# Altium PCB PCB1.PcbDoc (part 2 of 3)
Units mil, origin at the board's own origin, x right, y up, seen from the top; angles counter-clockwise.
Board outline 6299 x 3937 mil, 12 copper layers (TopLayer, VCC, GROUND, MidLayer1, MidLayer2, MidLayer3, MidLayer4, MidLayer5, MidLayer6, MidLayer7, MidLayer8, BottomLayer); 299 components, 467 nets, 2148 pads, 429 vias.
Unrouted connection lines stored in the file: 461.
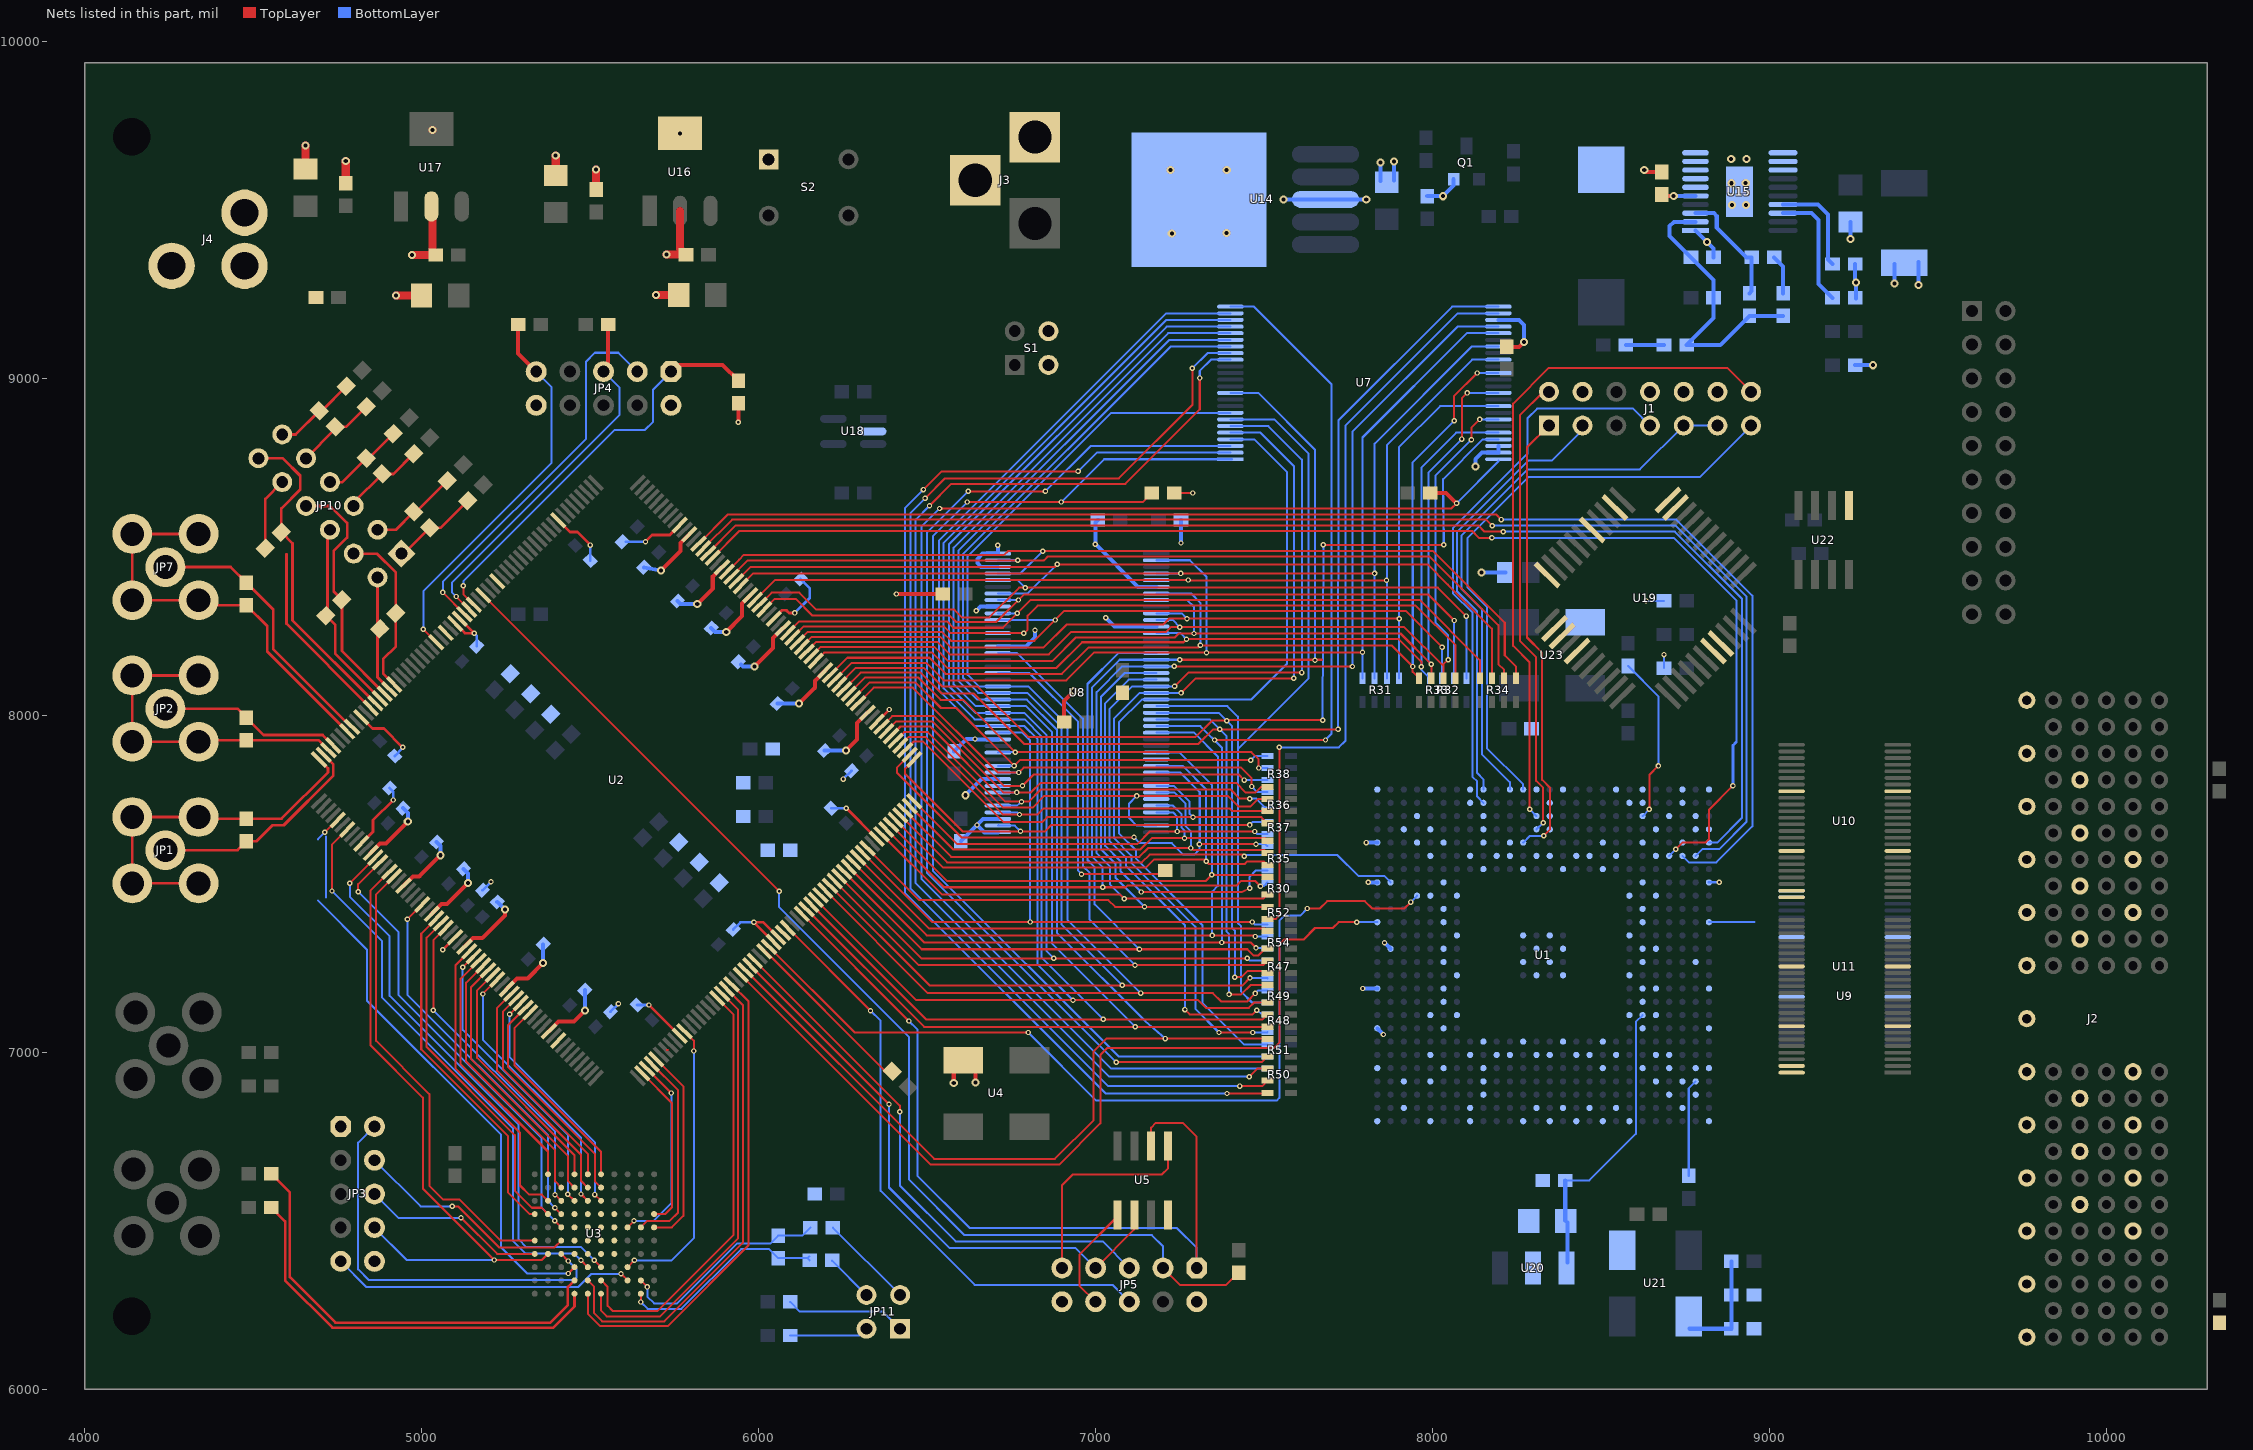
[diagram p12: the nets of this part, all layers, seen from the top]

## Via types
v1: diameter 16, hole 8, TopLayer to BottomLayer, 343 vias
v2: diameter 24, hole 12, TopLayer to BottomLayer, 84 vias
v3: diameter 56.69, hole 56.69, TopLayer to BottomLayer, 2 vias

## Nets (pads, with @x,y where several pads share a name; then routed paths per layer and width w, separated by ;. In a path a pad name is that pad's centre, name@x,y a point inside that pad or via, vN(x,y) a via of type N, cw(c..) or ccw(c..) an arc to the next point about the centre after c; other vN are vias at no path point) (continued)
101_RXLE: U2.11 U3.C3 | length 862.6
  TopLayer w6: U3.C3@5611.26,6362.74 v1(5631.52,6383) ; 5726.67,7007.33 5731.22,7007.33 ; U2.11@5780.14,7063.01 5808,7035.14 v1(5808,7004)
  BottomLayer w6: v1(5631.52,6383) 5742,6383 5808,6449 v1(5808,7004)
101_RXMODE: U2.19 U3.A5 | length 1305.6
  TopLayer w6: U3.A5@5532.52,6284 5532.52,6233.48 5549,6217 5708,6217 5939,6448 5939,7126.85 U2.19@5891.49,7174.36
101_RXOP: U2.2 U3.G1 | length 494.8
  TopLayer w6: U2.2@5654.86,6937.73 5743,6849.59 5743,6541 5722.22,6520.22 U3.G1@5690,6520.22
101_RXRATE: U2.193 U3.C5 | length 1650.6
  TopLayer w6: v1(4787,7502.18) U2.193@4862.85,7578.03 ; v1(5512.26,6383) U3.C5@5532.52,6362.74
  BottomLayer w6: v1(4787,7502.18) 4787,7462 4905,7344 4905,7168 5288,6785 5288,6445 5311,6422 5473.26,6422 v1(5512.26,6383)
101_RXST0: U2.3 U3.F3 | length 588.8
  TopLayer w6: U3.F3@5611.26,6480.85 v1(5630.41,6500) ; U2.3@5668.78,6951.65 v1(5741,6879.43)
  BottomLayer w6: v1(5630.41,6500) 5689,6500 5741,6552 v1(5741,6879.43)
101_RXST1: U2.4 U3.F2 | length 601.7
  TopLayer w6: U3.F2@5650.63,6480.85 5669.78,6500 5736,6500 5761,6525 5761,6887.27 U2.4@5682.7,6965.57
101_RXST2: U2.5 U3.F1 | length 598.9
  TopLayer w6: U3.F1@5690,6480.85 5742.85,6480.85 5777,6515 5777,6899.11 U2.5@5696.62,6979.49
101_SCSEL: U2.215 U3.K9 | length 762.7
  TopLayer w6: U2.215@5169.07,7271.8 5116,7218.73 5116,6965 5375.04,6705.96 U3.K9@5375.04,6638.33
101_SDASEL: U2.187 U3.C6 | length 1721.2
  TopLayer w6: v1(4734,7479) 4734,7616.21 U2.187@4782.79,7665 ; v1(5472.89,6383) U3.C6@5493.15,6362.74
  BottomLayer w6: v1(4734,7479) 4882,7331 4882,7164 5271,6775 5271,6441 5309,6403 5452.89,6403 v1(5472.89,6383)
101_SPDSEL: U2.185 U3.C7 | length 1777
  TopLayer w6: v1(4713,7653) 4749.38,7689.38 U2.185@4751.49,7689.38 ; v1(5435.04,6344) U3.C7@5453.78,6362.74
  BottomLayer w6: 4692,7451 4838,7305 4838,7153 5236,6755 5236,6421 5313,6344 v1(5435.04,6344) ; 4692,7632 v1(4713,7653) ; 4717,7459 4717,7640
101_T\R\S\T\Z\: JP3.8 U2.196 U3.D9 | length 1890.4
  TopLayer w6: U2.196@4904.6,7536.27 4848,7479.66 4848,7022 5004,6866 5004,6596 v1(5216,6384) 5356.93,6384 U3.D9@5375.04,6402.11
  BottomLayer w6: JP3.8@4860,6480 4956,6384 v1(5216,6384)
101_T\X\R\S\T\: U2.213 U3.H9 | length 892.3
  TopLayer w6: U2.213@5141.23,7299.64 5101,7259.4 5101,6952 5292,6761 5292,6605 5319,6578 5356.63,6578 U3.H9@5375.04,6559.59
101_TCK: JP3.4 U3.E8 | length 670.2
  TopLayer w6: v1(5091,6543) 5108,6543 5230,6421 5393.93,6421 U3.E8@5414.41,6441.48
  BottomLayer w6: JP3.4@4860,6680 4997,6543 v1(5091,6543)
101_TDI: JP3.6 U3.D10 | length 549.4
  TopLayer w6: v1(5117,6509) 5223.89,6402.11 U3.D10@5335.67,6402.11
  BottomLayer w6: JP3.6@4860,6580 4931,6509 v1(5117,6509)
101_TDO: JP3.9 U3.B3 | length 907.1
  TopLayer w6: v1(5591.63,6343) U3.B3@5611.26,6323.37
  BottomLayer w6: JP3.9@4760,6380 4836.11,6303.89 5465,6303.89 5504.11,6343 v1(5591.63,6343)
101_TMS: JP3.2 U3.D8 | length 1196.6
  TopLayer w6: U3.D8@5414.41,6402.11 v1(5435.52,6381)
  BottomLayer w6: JP3.2@4860,6780 4812,6732 4812,6356 4844,6324 5452,6324 5459,6331 5459,6357.52 v1(5435.52,6381)
101_TXCKSEL: U2.197 U3.E10 | length 1386
  TopLayer w6: U2.197@4918.52,7522.35 4865,7468.82 4865,7034 5023,6876 5023,6604 5063,6564 5112,6564 5234.52,6441.48 U3.E10@5335.67,6441.48
101_TXCLK: U2.208 U3.H8 | length 982
  TopLayer w6: v1(5035,7125) 5035,7332.6 U2.208@5071.64,7369.23 ; v1(5396,6578) U3.H8@5414.41,6559.59
  BottomLayer w6: v1(5035,7125) 5396,6764 v1(5396,6578)
101_TXCLKO+: U2.207 U3.G9 | length 1046.9
  TopLayer w6: U2.207@5057.72,7383.15 5015,7340.44 5015,7016 5276.59,6754.41 5276.59,6589.41 5327,6539 5356.26,6539 U3.G9@5375.04,6520.22
101_TXCLKO-: U2.206 U3.G10 | length 1043.6
  TopLayer w6: U2.206@5043.8,7397.07 4999,7352.27 4999,7009 5257.04,6750.96 5257.04,6583.96 5320.78,6520.22 U3.G10@5335.67,6520.22
101_TXCT0: U2.225 U3.J5 | length 669
  TopLayer w6: U2.225@5308.27,7132.6 5257,7081.34 5257,6956 5514,6699 5514,6617.48 U3.J5@5532.52,6598.96
101_TXCT1: U2.224 U3.H5 | length 713.2
  TopLayer w6: v1(5261,7113.18) U2.224@5294.35,7146.52 ; v1(5514,6578.11) U3.H5@5532.52,6559.59
  BottomLayer w6: v1(5261,7113.18) 5261,6986 5514,6733 v1(5514,6578.11)
101_TXD0: U2.216 U3.J8 | length 804.3
  TopLayer w6: U2.216@5188.11,7263 5132,7206.89 5132,6973 5396,6709 5396,6617.37 U3.J8@5414.41,6598.96
101_TXD1: U2.218 U3.K7 | length 730.3
  TopLayer w6: U2.218@5210.83,7230.04 5165,7184.21 5165,6984 5453.78,6695.22 U3.K7@5453.78,6638.33
101_TXD2: U2.217 U3.J7 | length 792.7
  TopLayer w6: U2.217@5196.91,7243.96 5147,7194.05 5147,6980 5434,6693 5434,6618.74 U3.J7@5453.78,6598.96
101_TXD3: U2.214 U3.H7 | length 877.3
  TopLayer w6: v1(5122,7252.56) U2.214@5155.15,7285.72 ; v1(5434,6579.37) U3.H7@5453.78,6559.59
  BottomLayer w6: v1(5122,7252.56) 5122,7067 5434,6755 v1(5434,6579.37)
101_TXD4: U2.223 U3.K6 | length 642.9
  TopLayer w6: U2.223@5280.43,7160.44 5241,7121.01 5241,6951 5493.15,6698.85 U3.K6@5493.15,6638.33
101_TXD5: U2.222 U3.J6 | length 704.5
  TopLayer w6: U2.222@5266.51,7174.36 5224,7131.85 5224,6945 5473,6696 5473,6619.11 U3.J6@5493.15,6598.96
101_TXD6: U2.219 U3.H6 | length 803.1
  TopLayer w6: v1(5182,7173.37) U2.219@5224.75,7216.12 ; v1(5473,6579.74) U3.H6@5493.15,6559.59
  BottomLayer w6: v1(5182,7173.37) 5182,7038 5473,6747 v1(5473,6579.74)
101_TXD7: U2.226 U3.K5 | length 605.7
  TopLayer w6: U2.226@5322.19,7118.68 5276,7072.5 5276,6961 5532.52,6704.48 U3.K5@5532.52,6638.33
101_TXMODE0: U2.20 U3.B6 | length 1425.6
  TopLayer w6: U3.B6@5493.15,6323.37 5512,6304.52 5512,6226 5536,6202 5720,6202 5953,6435 5953,7140.69 U2.20@5905.41,7188.28
101_TXMODE1: U2.21 U3.A6 | length 1445.9
  TopLayer w6: U3.A6@5493.15,6284 5493.15,6224.85 5530,6188 5730,6188 5970,6428 5970,7151.53 U2.21@5919.33,7202.2
101_TXOP: U2.203 U3.G8 | length 1125.9
  TopLayer w6: v1(4958,7394.79) U2.203@5002.04,7438.83 ; v1(5395.63,6539) U3.G8@5414.41,6520.22
  BottomLayer w6: v1(4958,7394.79) 4958,7171 5375,6754 5375,6559.63 v1(5395.63,6539)
101_TXPER: U2.194 U3.F8 | length 1359.6
  TopLayer w6: v1(4812,7477) 4812,7499.34 U2.194@4876.77,7564.11 ; v1(5395.26,6500) U3.F8@5414.41,6480.85
  BottomLayer w6: v1(4812,7477) 4932,7357 4932,7170 5356,6746 5356,6539.26 v1(5395.26,6500)
101_TXRATE: U2.18 U3.B5 | length 1278.8
  TopLayer w6: U3.B5@5532.52,6323.37 5552,6303.89 5552,6248 5568,6232 5699,6232 5925,6458 5925,7113.01 U2.18@5877.57,7160.44
AGND2: C153.1 C155.1 C157.1 C159.1 J4.2 R41.1 U19.32 U19.33
AOE#: R52.6 U2.50 U8.19 | length 2128.8
  TopLayer w6: U2.50@6322.99,7605.86 6476.86,7452 7038,7452 7058,7432 R52.6@7509.84,7432
  BottomLayer w6: v1(7145,7432) 7059.06,7517.94 7059.06,7560 7016,7603.06 7016,8055.37 7086.3,8125.67 U8.19@7180,8125.67
ARE#: R52.5 U2.53 U7.28 U8.18 | length 3929.1
  TopLayer w6: U2.53@6364.75,7647.62 6544.37,7468 7073,7468 v1(7085,7456) 7497.84,7456 R52.5@7509.84,7468 ; v1(7233.65,8145.35) 7762.35,8145.35 v1@7764,8147
  BottomLayer w6: v1(7085,7456) 7043.31,7497.69 7043.31,7551 7003,7591.31 7003,8068.94 7079.41,8145.35 v1(7233.65,8145.35) ; v1(7762,8145) 7762,8842 8073.7,9153.7 U7.28@8195.28,9153.7
AS_CONFDN: JP5.3 R26.1 U2.145 | length 3411.7
  TopLayer w6: U2.145@5182.99,8356.12 v1(6061,7478.11) ; JP5.3@7200,6360 7250,6310 7387,6310 R26.1@7420,6343
  BottomLayer w6: v1(6061,7478.11) 6061,7431 6446,7046 6446,6623 6611,6458 7167,6458 7200,6425 JP5.3@7200,6360
AS_DCLK: JP5.1 U2.36 U5.6 | length 2499.1
  TopLayer w6: U2.36@6128.12,7410.99 v1(6446,7093.11) ; U5.6@7165,6722.36 7165,6777 7179,6791 7259,6791 7300,6750 JP5.1@7300,6360
  BottomLayer w6: v1(6446,7093.11) 6471,7068.11 6471,6634 6626,6479 7241,6479 7300,6420 JP5.1@7300,6360
AS_NCONFIG: JP5.5 R27.1 U2.26 | length 1627.4
  TopLayer w6: U2.26@5988.93,7271.8 6419,6841.73 v1(6419,6824)
  BottomLayer w6: v1(6419,6824) 6419,6605 6585,6439 7021,6439 JP5.5@7100,6360
AWE#: R30.7 U2.54 U7.11 U8.17 | length 3489.6
  TopLayer w6: U2.54@6378.67,7661.54 6550.21,7490 7089,7490 7094,7495 7418,7495 7432,7509 7473,7509 v1(7489,7493) ; v1(7249.96,8165.04) 7671.04,8165.04 7672,8166
  BottomLayer w6: v1(7021,7490) 7021,7549.56 6989,7581.56 6989,8082.5 7071.54,8165.04 v1(7249.96,8165.04) ; U7.11@7400,8956.85 7482.15,8956.85 7651,8788 v1(7651,8164) ; v1(7489,7493) 7498.84,7493 R30.7@7509.84,7504
BE0#: R47.5 U2.45 U8.16 | length 2453.9
  TopLayer w6: U2.45@6253.4,7536.27 6483.66,7306 7450,7306 7468,7288 7483.34,7288 R47.5@7503.34,7308
  BottomLayer w6: v1(7130,7306) 6997,7439 6997,7549.78 6976,7570.78 6976,8093.13 7067.6,8184.73 U8.16@7180,8184.73
BE1#: R47.6 U2.43 U8.71 | length 2520.8
  TopLayer w6: U2.43@6225.56,7508.43 6474.99,7259 7496.84,7259 R47.6@7509.84,7272
  BottomLayer w6: U8.71@6710,8184.73 6767.27,8184.73 6962,7990 6962,7553.03 6982,7533.03 6982,7394 v1(7117,7259)
BE2#: R54.7 U2.47 U8.28 | length 2070
  TopLayer w6: U2.47@6281.23,7564.11 6498.34,7347 7471,7347 v1(7474,7344)
  BottomLayer w6: U8.28@7180,7948.51 7292.49,7948.51 7363,7878 7363,7494 7346,7477 v1(7346,7347) ; v1(7474,7344) R54.7@7509.84,7344
BE3#: R54.8 U2.49 U8.59 | length 1932.6
  TopLayer w6: U2.49@6309.07,7591.94 6514.02,7387 v1(7465,7387)
  BottomLayer w6: U8.59@6710,7948.51 6783,7948.51 6806,7925.51 v1(6806,7387) ; v1(7465,7387) 7472,7380 R54.8@7509.84,7380
CE0#: R30.8 U8.20 | length 1204.4
  TopLayer w6: v1(7135,7476) 7434,7476 v1(7457,7487)
  BottomLayer w6: v1(7135,7476) 7073.82,7537.18 7073.82,7567 7028,7612.82 7028,8035.87 7098.11,8105.98 U8.20@7180,8105.98 ; v1(7457,7487) 7457,7521 7476,7540 R30.8@7509.84,7540
CE1#: R52.7 U7.26 | length 2270.4
  TopLayer w6: R52.7@7509.84,7396 7535,7396 7545,7406 v1(7545,7905)
  BottomLayer w6: v1(7545,7905) 7722,7905 7741,7924 7741,8860 8074.07,9193.07 U7.26@8195.28,9193.07
CE2#: R52.8 U2.48 | length 1305
  TopLayer w6: U2.48@6295.15,7578.03 6506.18,7367 7502.84,7367 R52.8@7509.84,7360
CE3#: U1.L26 U2.23 | length 2709.1
  TopLayer w6: U2.23@5947.17,7230.04 6510.21,6667 6892,6667 7014.29,6789.29 7014.29,6992.29 7035,7013 7529,7013 7545,7029 7545,7320 7560,7335 7617,7335 7651,7369 7704,7369 7721.3,7386.3 v1(7775.3,7386.3)
  BottomLayer w6: v1(7775.3,7386.3) U1.L26@7835.75,7386.3
CVBS: J4.1 R40.2 R41.2
DATA: JP5.7 U2.25 U5.2 | length 1746.8
  TopLayer w6: U2.25@5975.01,7257.88 v1(6387,6845.89) ; JP5.7@7000,6360 7115,6475 U5.2@7115,6517.64
  BottomLayer w6: v1(6387,6845.89) 6387,6599 6567,6419 6941,6419 JP5.7@7000,6360
DSP_CLKIN: R82.2 U1.AC2 | length 288.9
  BottomLayer w6: R82.2@8760,6633.46 8760,6893.23 U1.AC2@8780.63,6913.86
DSP_T\R\S\T\: J1.2 U1.D14 | length 1386.9
  TopLayer w6: v1(8328,7681.7) 8328,7785 8307,7806 8307,8173 8259,8221 8259,8890 8329,8960 J1.2@8352,8960
  BottomLayer w6: U1.D14@8308.19,7661.89 v1(8328,7681.7)
DSP_TCLK: J1.9 J1.11 U1.A16 | length 1707.5
  BottomLayer w6: U1.A16@8229.45,7780 8229.45,7801.55 8146,7885 8146,8315 8086,8375 8086,8534 8282,8730 8615,8730 J1.9@8745,8860 J1.11@8845,8860
DSP_TDI: J1.3 U1.A18 | length 1308.1
  BottomLayer w6: U1.A18@8150.71,7780 8150.71,7810.29 8132,7829 8132,8309 8072,8369 8072,8544 8284,8756 8354,8756 8445,8847 J1.3@8445,8860
DSP_TDO: J1.7 U1.B18 | length 1666.2
  BottomLayer w6: U1.B18@8150.71,7740.63 8132,7759.34 8132,7804 8119,7817 8119,8304 8060,8363 8060,8555 8281,8776 8281,8881 8310,8910 8595,8910 J1.7@8645,8860
DSP_TMS: J1.1 U1.E15 | length 1349.2
  TopLayer w6: v1(8329.7,7642.7) 8348,7661 8348,7786 8325,7809 8325,8186 8280,8231 8280,8795 J1.1@8345,8860
  BottomLayer w6: U1.E15@8268.82,7622.52 8289,7642.7 v1(8329.7,7642.7)
EA03: R47.7 U2.77 U7.45 U8.25 | length 3941.6
  TopLayer w6: U2.77@6239.48,8091.65 6288.82,8141 6490,8141 6545.66,8085.34 6650.66,8085.34 6800,7936 7297,7936 7345.3,7984.3 v1(7388.7,7984.3) 7390.2,7985.8 v1(7673.8,7985.8) ; v1(7413,7223) 7432,7223 7450,7241 7504.84,7241 R47.7@7509.84,7236 ; v1(7675.8,8506.2) v1(8033,8506.2)
  BottomLayer w6: U8.25@7180,8007.56 7365.44,8007.56 7405,7968 7405,7369 7412,7362 ; v1(7413,7223) 7413,7362 ; v1(7673.8,7985.8) v1(7675.8,8506.2) ; v1(8033,8506.2) 8031,8701 8149.06,8819.06 U7.45@8195.28,8819.06
EA04: R47.8 U2.76 U7.25 U8.26 | length 4248
  TopLayer w6: U2.76@6253.4,8077.73 6302.66,8127 6481,8127 6543.09,8064.91 6638.09,8064.91 6788,7915 7305,7915 7348.49,7958.49 v1(7719.49,7958.49) ; v1(7396,7172) 7432,7172 7460,7200 R47.8@7509.84,7200
  BottomLayer w6: U8.26@7180,7987.88 7339.12,7987.88 7389,7938 7389,7358 7396,7351 v1(7396,7172) ; v1(7719.49,7958.49) 7720,8839 7720,8875 8057.76,9212.75 U7.25@8195.28,9212.75
  other v1: 7368.51,7958.49
EA05: R54.6 U2.46 U7.24 U8.27 | length 3930.3
  TopLayer w6: U2.46@6267.32,7550.19 6491.5,7326 7460,7326 v1(7476,7310) ; v1(7353,7927) v1(7682,7927)
  BottomLayer w6: U8.27@7180,7968.19 7310.81,7968.19 7375,7904 7375,7327 v1(7374,7326) ; U7.24@7400,9212.75 7470,9212.75 7700,8982.75 7700,7945 v1(7682,7927) ; v1(7476,7310) 7507.84,7310 R54.6@7509.84,7308
EA06: R48.5 U2.39 U7.23 U8.60 | length 4238.7
  TopLayer w6: U2.39@6169.88,7452.75 6467.63,7155 7304,7155 7327,7132 7455,7132 7471,7148 R48.5@7509.84,7148
  BottomLayer w6: v1(6933,7155) 6827,7261 6827,7930.19 6789,7968.19 6640.81,7968.19 6535,8074 6535,8518 7210.07,9193.07 U7.23@7400,9193.07
EA07: R48.6 U2.38 U7.22 U8.61 | length 4322.8
  TopLayer w6: U2.38@6155.96,7438.83 6496.79,7098 7495.84,7098 R48.6@7509.84,7112
  BottomLayer w6: v1(7023,7098) 6840,7281 6840,7937 6789.12,7987.88 6641.12,7987.88 6549,8080 6549,8512 7210.39,9173.39 U7.22@7400,9173.39
EA08: R54.5 U2.44 U7.21 U8.62 | length 3919.3
  TopLayer w6: U2.44@6239.48,7522.35 6482.82,7279 v1(7450,7279)
  BottomLayer w6: v1(6876,7279) 6854,7301 6854,7942 6788.44,8007.56 6643.44,8007.56 6565,8086 6565,8508 7210.7,9153.7 U7.21@7400,9153.7 ; v1(7450,7279) 7457,7272 R54.5@7509.84,7272
EA09: R48.7 U2.37 U7.20 U8.63 | length 4329.9
  TopLayer w6: U2.37@6142.04,7424.91 6490.95,7076 R48.7@7509.84,7076
  BottomLayer w6: v1(7118,7076) 6870,7324 6870,7951 6793.76,8027.24 6643.76,8027.24 6579,8092 6579,8498 7215.02,9134.01 U7.20@7400,9134.01
EA10: R48.8 U2.24 U7.19 U8.64 | length 4905.5
  TopLayer w6: U2.24@5961.09,7243.96 6521.05,6684 6879,6684 6994,6799 6994,7003 7032,7041 7508.84,7041 R48.8@7509.84,7040
  BottomLayer w6: v1(7207,7041) 7148,7092 6886,7354 6885,7354 6885,7958 6796.07,8046.93 6649.07,8046.93 6593,8103 6593,8488 7219.33,9114.33 U7.19@7400,9114.33
EA11: R49.8 U2.42 U7.18 U8.65 | length 4039.2
  TopLayer w6: U2.42@6211.64,7494.51 6507.15,7199 7436,7199 v1(7458,7221)
  BottomLayer w6: v1(7079,7199) 6899,7379 6899,7965 6797.39,8066.61 6651.39,8066.61 6607,8111 6607,8479 7222.65,9094.65 U7.18@7400,9094.65 ; v1(7458,7221) 7508.84,7221 R49.8@7509.84,7220
EA12: R49.7 U2.41 U7.8 U8.66 | length 4013.7
  TopLayer w6: U2.41@6197.72,7480.59 6502.31,7176 7348,7176 7373,7151 7450,7151 v1(7474,7175)
  BottomLayer w6: v1(7134,7176) 6916,7394 6916,7971 6800.7,8086.3 6653.7,8086.3 6620,8120 6620,8472 7045.8,8897.8 U7.8@7400,8897.8 ; v1(7474,7175) 7483,7184 R49.7@7509.84,7184
EA13: R49.6 U7.7 U8.24 | length 2403.5
  BottomLayer w6: U8.24@7180,8027.24 7390.76,8027.24 7422,7996 7422,7384 7432,7374 7432,7180 7464,7148 R49.6@7509.84,7148 ; U7.7@7400,8878.11 7529.89,8878.11 7632,8776 7632,8110 7422,7900
EA14: R49.5 U7.6 U8.21 | length 2745.9
  TopLayer w6: v1(7234.3,8086.3) 7275,8127 v1(7612,8127) ; v1(7265,7127) 7279,7113 7466,7113 v1(7478,7125)
  BottomLayer w6: v1(7234.3,8086.3) 7108.94,8086.3 7041,8018.36 7041,7627.57 7089.57,7579 7089.57,7553.43 7265,7378 v1(7265,7127) ; U7.6@7400,8858.42 7512.57,8858.42 7612,8759 v1(7612,8127) ; v1(7478,7125) R49.5@7496.34,7112 ; R49.5@7496.34,7110 7507.84,7110 R49.5@7509.84,7112
EA15: R51.8 U7.5 U8.22 | length 2647.1
  TopLayer w6: v1(7253.61,8066.61) 7297,8110 v1(7588,8110) ; v1(7366,7059) v1(7466,7059)
  BottomLayer w6: v1(7253.61,8066.61) 7130.59,8066.61 7054,7990.02 7054,7636.3 7106.3,7584 7106.3,7562.7 7296,7373 7296,7129 v1(7366,7059) ; U7.5@7400,8838.74 7489.26,8838.74 7588,8740 v1(7588,8110) ; v1(7466,7059) 7508.84,7059 R51.8@7509.84,7060
EA16: R51.7 U7.4 U8.23 | length 2526.2
  BottomLayer w6: U7.4@7400,8819.06 7470.94,8819.06 7568,8722 7568,8153.93 7461,8046.93 7136.93,8046.93 7069,7979 7069,7650 7120,7599 7120,7575 7317,7378 7317,7147 7440,7024 R51.7@7509.84,7024
EA17: R50.5 U7.3 | length 3270.7
  TopLayer w6: v1(6622,8665) v1(6851,8665) ; v1(7061,6971) 7492.84,6971 R50.5@7509.84,6988
  BottomLayer w6: v1(6622,8665) 6500,8543 6500,7532 v1@7064,6968 ; v1(6851,8665) 6985.37,8799.37 U7.3@7400,8799.37
EA18: R50.8 U7.2 | length 3501.6
  TopLayer w6: v1(6489,8670) 6543,8724 v1(6948,8724) ; v1(7390,6878) 7507.84,6878 R50.8@7511.84,6882
  BottomLayer w6: v1(6489,8670) 6434,8615 6434,7474 7030,6878 v1(7390,6878) ; v1(6948,8724) 7003.69,8779.68 U7.2@7400,8779.68
EA19: R51.6 R59.2 U7.1 | length 3474.6
  TopLayer w6: v1(6619,8633) 7139.54,8633 R59.2@7166.54,8660
  BottomLayer w6: v1(6619,8633) 6517,8531 6517,7539 7068,6988 R51.6@7509.84,6988 ; v1(6898,8633) 7025,8760 U7.1@7404,8760
EA20: R51.5 R58.1 U7.48 | length 4190.8
  TopLayer w6: v1(6537,8614) 8056,8614 v1(8071,8629)
  TopLayer w12: R58.1@7993.46,8660 8040,8660 v1(8071,8629)
  BottomLayer w6: v1(6537,8614) 6483,8560 6483,7515 7046,6952 R51.5@7509.84,6952 ; v1(8071,8629) 8195.28,8753.28 U7.48@8195.28,8756.28
EA21: R50.7 S1.3 U7.17 | length 3632.4
  TopLayer w6: v1(6494,8644) 6553,8703 7069,8703 7287,8921 v1(7287,9030) ; v1(7428,6900) 7493.84,6900 R50.7@7509.84,6916
  BottomLayer w6: v1(6494,8644) 6451,8601 6451,7486 7037,6900 v1(7428,6900) ; v1(7287,9030) 7331.96,9074.96 U7.17@7400,9074.96
EA22: R50.6 S1.4 U7.16 | length 3567.8
  TopLayer w6: v1(6507,8622) 6572,8687 7088,8687 7309,8908 v1(7309,9001) ; v1(7456,6928) 7480,6952 R50.6@7509.84,6952
  BottomLayer w6: v1(6507,8622) 6466,8581 6466,7502 7040,6928 v1(7456,6928) ; v1(7309,9001) 7309,9022 7342.27,9055.27 U7.16@7400,9055.27
ECLKIN: U1.H25 U2.57 | length 1554
  TopLayer w6: U2.57@6420.43,7703.3 6559.73,7564 7137,7564 7160,7587 7436,7587 v1(7441,7582)
  BottomLayer w6: v1@7444.63,7585.63 7717.52,7585.63 7779.53,7523.62 7855.9,7523.62 U1.H25@7875.12,7504.41
ECLKOUT1: R55.2 U8.68 | length 1018.5
  TopLayer w6: v1(6958,7529) 7195.54,7529 R55.2@7214.54,7548
  BottomLayer w6: U8.68@6710,8125.67 6803.33,8125.67 6948,7981 6948,7539 v1(6958,7529)
ECLKOUT2: U1.J23 U2.29 | length 2690.5
  TopLayer w6: U2.29@6030.69,7313.56 6285.24,7059 v1(6800,7059) ; v1(7628,7427) 7665,7427 7687,7449 7799,7449 7821,7427 7916,7427 v1(7935,7446)
  BottomLayer w6: v1(6800,7059) 7002,6857 7537,6857 7545,6865 7545,7391 7560,7406 7607,7406 v1(7628,7427) ; v1(7935,7446) U1.J23@7953.86,7465.04
ED00: R31.5 U2.78 U7.29 U8.2 | length 3283.3
  TopLayer w6: U2.78@6225.56,8105.57 6275.99,8156 6497,8156 6549,8104 6913,8104 6995,8186 7790,8186 v1(7792,8187)
  BottomLayer w6: U8.2@7180,8460.32 7279.69,8460.32 7329,8411 v1(7329,8186) ; R31.5@7792,8110.16 7792,8824.48 8101.53,9134.01 U7.29@8195.28,9134.01
ED01: R31.6 U2.98 U7.31 U8.4 | length 3151.6
  TopLayer w6: U2.98@5947.17,8383.96 5984.47,8421.26 v1(7827.76,8421.26)
  BottomLayer w6: U8.4@7180.31,8421.26 v1(7252.95,8421.26) ; R31.6@7828,8110.16 7828,8806.35 8116.3,9094.65 U7.31@8195.28,9094.65
ED02: R31.7 U2.95 U7.33 U8.5 | length 3122
  TopLayer w6: U2.95@5988.93,8342.2 6048.3,8401.57 v1(7274.61,8401.57) 7275.59,8400.59 v1(7863.19,8400.59)
  BottomLayer w6: U8.5@7180,8401.26 7180.31,8401.57 v1(7274.61,8401.57) ; R31.7@7864,8110.16 7864,8802 8117.27,9055.27 U7.33@8195.28,9055.27
ED03: R33.8 U2.79 U7.35 U8.7 | length 3156.5
  TopLayer w6: U2.79@6211.64,8119.49 6263.15,8171 6507,8171 6555,8123 6900,8123 6979,8202 7305,8202 v1(7311,8208) 7878,8208 v1(7941,8145) 7940.94,8129.21 R33.8@7960,8110.16 ; v1(8063.98,8874.02) 8063.98,8947.83 v1(8132.05,9015.91)
  BottomLayer w6: U8.7@7180,8361.89 7283.11,8361.89 7311,8334 v1(7311,8208) ; v1(7941,8145) 7940.94,8750.98 v1(8063.98,8874.02) ; v1(8132.05,9015.91) U7.35@8195.28,9015.91
ED04: R33.7 U2.83 U7.38 U8.8 | length 3130.5
  TopLayer w6: U2.83@6155.96,8175.17 6183.79,8203 6521,8203 6563,8161 6871,8161 6941,8231 7235,8231 7247,8243 7904.64,8243 v1@7996,8151.64 ; R33.7@7996,8110.16 v1@7996,8151.64 ; v1(7996.13,8151.64) v1@7996,8151.64 ; v1(8086.61,8819.88) 8086.61,8940.94 v1(8102.52,8956.85)
  BottomLayer w6: U8.8@7180,8342.2 7271.8,8342.2 7292,8322 v1(7292,8243) ; v1(7996.13,8151.64) 7988,8159.76 7988,8721.27 v1(8086.61,8819.88) ; v1(8102.52,8956.85) U7.38@8195.28,8956.85
ED05: R31.8 U2.85 U7.40 U8.10 | length 2962.4
  TopLayer w6: U2.85@6128.12,8203.01 6158.11,8233 6539,8233 6570,8202 6846,8202 6913.72,8269.72 7200.72,8269.72 7217.81,8286.81 v1(7900.59,8286.81)
  BottomLayer w6: U8.10@7180,8302.83 7255.24,8302.83 v1(7271.26,8286.81) ; R31.8@7900,8110.16 7900,8795 8022.48,8917.48 U7.40@8195.28,8917.48 ; v1@7900,8287.4 v1(7900.59,8286.81)
ED06: R33.6 U2.84 U7.42 U8.11 | length 2977.6
  TopLayer w6: U2.84@6142.04,8189.09 6170.95,8218 6530,8218 6567,8181 6861,8181 6928,8248 7209.19,8248 7223,8261.81 7915.35,8261.81 7975.39,8201.77 7976.38,8202.76 8032,8147.13 ; R33.6@8032,8110.16 8032,8151.09 v1(8046.26,8165.35) ; v1(8115.16,8818.16) 8115.16,8853.35 v1(8139.92,8878.11)
  BottomLayer w6: U8.11@7180,8283.15 7228.66,8283.15 v1(7250,8261.81) ; v1(8046.26,8165.35) 8046.26,8238.19 8008,8276.45 8008,8711 v1(8115.16,8818.16) ; v1(8139.92,8878.11) U7.42@8195.28,8878.11
ED07: R32.5 U2.82 U7.44 U8.13 | length 2908.2
  TopLayer w6: U2.82@6169.88,8161.25 6194.63,8186 6515,8186 6560,8141 6884,8141 6960,8217 7260.78,8217 v1(7269.78,8226) 7900,8226 7966.54,8159.46 v1(7966.54,8144)
  BottomLayer w6: U8.13@7180,8243.78 7252,8243.78 v1(7269.78,8226) ; R32.5@7992,8110.16 7966.54,8135.62 7966.54,8735.24 8070.04,8838.74 U7.44@8195.28,8838.74
ED08: R33.5 U2.87 U8.74 | length 2271.5
  TopLayer w6: U2.87@6100.28,8230.85 6133.44,8264 6550,8264 6570.22,8243.78 v1(6787.09,8243.78) 6798,8254.69 6798,8296 6827.79,8325.79 7949.8,8325.79 8068,8207.59 R33.5@8068,8110.16
  BottomLayer w6: U8.74@6710,8243.78 v1(6787.09,8243.78)
ED09: R32.6 U2.86 U8.76 | length 2282.1
  TopLayer w6: U2.86@6114.2,8216.93 6145.27,8248 6544,8248 6571,8221 6818.44,8221 6907.48,8310.04 7920.28,8310.04 v1(8028,8202.32)
  BottomLayer w6: U8.76@6710,8283.15 v1(6880.59,8283.15) ; R32.6@8028,8110.16 v1(8028,8202.32)
ED10: R34.8 U2.88 U8.77 | length 2295.1
  TopLayer w6: U2.88@6086.36,8244.77 6120.6,8279 6559,8279 6578,8260 6724.57,8260 6807.09,8342.52 7961.61,8342.52 8140,8164.13 R34.8@8140,8110.16
  BottomLayer w6: U8.77@6710,8302.83 v1(6767.4,8302.83)
ED11: R32.7 U2.93 U8.79 | length 2387.5
  TopLayer w6: U2.93@6016.77,8314.36 6048.4,8346 6110,8346 6160,8296 6567,8296 6586,8277 6705.78,8277 6788.03,8359.25 7986.22,8359.25 v1(8064,8281.47)
  BottomLayer w6: U8.79@6710,8342.2 v1(6770.98,8342.2) ; R32.7@8064,8110.16 v1(8064,8281.47)
ED12: R34.7 U2.99 U8.80 | length 2700.9
  TopLayer w6: U2.99@5933.25,8397.88 5975.37,8440 6878,8440 v1(6886,8448) 7985.07,8448 8044.98,8388.09 8176,8257.07 R34.7@8176,8110.16
  BottomLayer w6: U8.80@6710,8361.89 6798.9,8361.89 v1(6886,8448)
ED13: R32.8 U2.94 U8.82 | length 2487.9
  TopLayer w6: U2.94@6002.85,8328.28 6038.56,8364 6121,8364 6171,8314 6581,8314 ; 6581,8313 6603,8291 6685,8291 6772.94,8378.94 8015.75,8378.94 v1(8100,8294.68)
  BottomLayer w6: U8.82@6710,8401.26 6768.74,8401.26 v1(6791.06,8378.94) ; R32.8@8100,8110.16 v1(8100,8294.68)
ED14: R34.5 U2.101 U8.83 | length 2764
  TopLayer w6: U2.101@5903.69,8424 U2.101@5905.41,8425.72 5942.07,8462.38 5955.69,8476 6728.8,8476 6740,8487.2 8001.8,8487.2 8214,8275 8214,8178 8248,8144 R34.5@8248,8110.16
  BottomLayer w6: U8.83@6710,8420.94 6776.94,8420.94 v1(6843.2,8487.2)
ED15: R34.6 U2.100 U8.85 | length 2609.3
  TopLayer w6: U2.100@5919.33,8411.8 5967.53,8460 6847.31,8460 ; 6847,8460.32 6858.69,8472 7990.6,8472 8195,8267.6 8195,8152 8212,8135 R34.6@8212,8110.16
  BottomLayer w6: U8.85@6710,8460.32 v1(6769.37,8460.32)
ED16: R35.8 U2.55 U8.31 | length 1668.5
  TopLayer w6: U2.55@6392.59,7675.46 6560.05,7508 7326,7508 v1(7345,7527) 7503.84,7526 R35.8@7509.84,7520
  BottomLayer w6: U8.31@7180,7889.45 7249.55,7889.45 7345,7794 v1(7345,7527)
ED17: R35.7 U2.56 U8.33 | length 1576
  TopLayer w6: U2.56@6406.51,7689.38 6547.89,7548 7149,7548 7174,7573 7322,7573 7336,7559 7442,7559 7450,7567 7498.84,7567 R35.7@7509.84,7556
  BottomLayer w6: U8.33@7180,7850.08 7258,7850.08 7328,7780.08 v1(7328,7567)
ED18: R37.5 U2.62 U8.34 | length 1600.7
  TopLayer w6: U2.62@6448.27,7882.86 6411,7845.59 6411,7829 6602,7638 v1(7114,7638) ; v1(7308,7618) v1(7476,7618)
  BottomLayer w6: v1(7114,7638) 7131,7621 7226,7621 7260,7587 7293,7587 7308,7602 v1(7308,7618) 7309,7619 7309,7772 7250.6,7830.4 U8.34@7180,7830.4 ; v1(7476,7618) 7503.84,7618 R37.5@7509.84,7612
ED19: R36.8 U2.63 U8.36 | length 1367.2
  TopLayer w6: U2.63@6434.35,7896.78 6459.57,7922 6488,7922 6727,7683 6841,7683 6856,7698 7491.84,7698 R36.8@7509.84,7680
  BottomLayer w6: U8.36@7180,7791.02 7232,7791.02 7279,7744.02 7279,7708 v1(7289,7698)
ED20: R35.6 U2.58 U8.37 | length 1379.4
  TopLayer w6: U2.58@6434.35,7717.22 6571.57,7580 7130,7580 7156.52,7606.52 v1(7282.48,7606.52) ; 7288.61,7600.39 7501.45,7600.39 R35.6@7509.84,7592
  BottomLayer w6: U8.37@7180,7771.34 7233.66,7771.34 7267,7738 7267,7671.58 7282.48,7656.1 v1(7282.48,7606.52)
ED21: R35.5 U2.59 U8.39 | length 1292.2
  TopLayer w6: U2.59@6448.27,7731.14 6577.41,7602 7133,7602 7166.83,7635.83 7502.02,7635.83 R35.5@7509.84,7628
  BottomLayer w6: U8.39@7180,7731.97 7229.64,7731.97 7255,7706.61 7255,7666.61 7263.78,7657.83 v1(7263.78,7635.83)
ED22: R37.6 U2.60 U8.40 | length 1230.5
  TopLayer w6: U2.60@6462.19,7745.06 6589.25,7618 7123,7618 7160.51,7655.51 v1(7472.44,7655.51)
  BottomLayer w6: U8.40@7180,7712.28 7229.64,7712.28 7242.13,7699.8 v1(7242.13,7655.51) ; v1(7472.44,7655.51) 7479.95,7648 R37.6@7509.84,7648
ED23: R36.6 U2.65 U8.42 | length 1408.2
  TopLayer w6: U2.65@6406.51,7924.62 6431.89,7950 6502,7950 6726,7726 6813,7726 6848,7761 7392,7761 7423,7730 7460,7730 7482,7752 R36.6@7509.84,7752
  BottomLayer w6: v1(7122,7761) 7099,7738 7099,7696 7122.09,7672.91 U8.42@7180,7672.91
ED24: R37.7 U2.61 U8.45 | length 1288
  TopLayer w6: U2.61@6462.19,7868.94 6435,7841.75 6435,7826 6605,7656 6850,7656 6869,7675 v1(7457,7675)
  BottomLayer w6: U8.45@6712.09,7675 U8.45@6710,7672.91 6760.09,7672.91 v1(6777,7656) ; v1(7457,7675) 7466,7684 R37.7@7509.84,7684
ED25: R36.7 U2.64 U8.47 | length 1272
  TopLayer w6: U2.64@6420.43,7910.7 6445.73,7936 6494,7936 6724,7706 6828,7706 6845,7723 7398,7723 7405,7716 R36.7@7509.84,7716
  BottomLayer w6: U8.47@6710,7712.28 6768,7712.28 v1(6774.28,7706)
ED26: R37.8 U2.66 U8.48 | length 1335.8
  TopLayer w6: U2.66@6392.59,7938.54 6421.05,7967 6509,7967 6731.94,7744.06 v1(6780.15,7744.06) ; v1@6780.16,7744.38 6801.06,7744.06 6837,7780 7401,7780 7428,7753 v1(7457,7753)
  BottomLayer w6: U8.48@6710,7731.97 6766.06,7731.97 v1(6780.15,7744.06) ; v1(7457,7753) 7476.84,7753 R37.8@7509.84,7720
ED27: R36.5 U2.67 U8.50 | length 1317.8
  TopLayer w6: U2.67@6378.67,7952.46 6408.21,7982 6515,7982 6725.66,7771.34 6808.34,7771.34 6837,7800 7416.76,7800 7446.01,7770.75 7473.75,7770.75 7491,7788 R36.5@7509.84,7788
  BottomLayer w6: U8.50@6710,7771.34 v1(6766,7771.34)
ED28: R38.6 U2.68 U8.51 | length 1338.2
  TopLayer w6: U2.68@6364.75,7966.38 6396.37,7998 6521,7998 6727.98,7791.02 v1(6783.15,7791.02) 6817.13,7825 7424,7825 v1(7441,7808)
  BottomLayer w6: U8.51@6710,7791.02 v1(6783.15,7791.02) ; v1(7441,7808) R38.6@7509.84,7808
ED29: R38.5 U2.73 U8.53 | length 1450.9
  TopLayer w6: U2.73@6295.15,8035.97 6341.18,8082 6458,8082 6709.6,7830.4 v1(6772,7830.4) 6786.6,7845 7432,7845 7463,7814 v1(7463,7789)
  BottomLayer w6: U8.53@6710,7830.4 v1(6772,7830.4) ; v1(7463,7789) 7480,7772 R38.5@7509.84,7772
ED30: R38.8 U2.74 U8.54 | length 1411.6
  TopLayer w6: U2.74@6281.23,8049.89 6329.34,8098 6465,8098 6541.12,8021.88 6586.2,8021.88 v1(6758,7850.08) 6774.92,7867 v1(7460.5,7867)
  BottomLayer w6: U8.54@6710,7850.08 v1(6758,7850.08) ; v1(7460.5,7867) 7473.5,7880 R38.8@7509.84,7880
ED31: R38.7 U2.75 U8.56 | length 1441.5
  TopLayer w6: U2.75@6267.32,8063.81 6316.5,8113 6473,8113 6540.12,8045.88 6606.68,8045.88 v1(6761.81,7890.75) 7462.25,7890.75 7483.76,7869.24 v1(7483.76,7844)
  BottomLayer w6: U8.56@6710,7889.45 6711.3,7890.75 v1(6761.81,7890.75) ; v1(7483.76,7844) R38.7@7509.84,7844
EMU0: J1.13 U1.A15 | length 1794.2
  BottomLayer w6: U1.A15@8268.82,7780 8268.82,7795.18 8161,7903 8161,8322 8104,8379 8104,8527 8284,8707 8792,8707 J1.13@8945,8860
EMU1: J1.14 U1.C14 | length 2031.7
  TopLayer w6: v1(8288,7721.45) 8288,8157 8239,8206 8239,8925 8345,9031 8874,9031 J1.14@8945,8960
  BottomLayer w6: v1(8288,7721.45) U1.C14@8308.19,7701.26
FPGA_ASDO: JP5.9 U5.5 | length 647.5
  TopLayer w6: JP5.9@6900,6360 6900,6605 6933,6638 7197,6638 7215,6656 U5.5@7215,6722.36
FPGA_NCSO: JP5.8 U5.1 | length 324.3
  TopLayer w6: JP5.8@7000,6260 6952,6308 6952,6400 7065,6513 U5.1@7065,6517.64
GCLK0: R25.2 U2.153
GCLK1: R24.2 U2.28 | length 510.6
  TopLayer w6: U2.28@6016.77,7299.64 6020.36,7299.64 6376.34,6943.66 R24.2@6372.74,6943.66
GND: C5.1 C6.1 C7.1 C8.1 C9.1 C10.1 C11.1 C12.1 C13.1 C14.1 C15.1 C16.1 C17.1 C18.1 C19.1 C20.1 C21.1 C22.1 C23.1 C24.1 C25.1 C26.1 C32.1 C36.1 C37.2 C38.2 C39.2 C40.2 C41.2 C45.2 C46.2 C47.2 C48.2 C49.2 C54.1 C55.2 C56.2 C57.2 C58.2 C59.2 C64.1 C65.2 C66.2 C67.2 C68.2 C69.2 C73.2 C74.2 C75.2 C76.2 C77.2 C82.2 C83.2 C84.2 C85.2 C86.2 C95.1 C96.1 C97.2 C98.2 C99.2 C100.2 C101.2 C103.2 C104.2 C105.2 C106.2 C107.2 C108.2 C109.2 C110.2 C111.2 C112.2 C114.2 C115.2 C116.2 C117.2 C119.2 C120.2 C121.2 C123.2 C124.2 C125.1 C126.1 C127.1 C128.1 C129.1 C130.1 C131.1 C132.1 C133.1 C134.2 C135.2 C136.2 C137.2 C138.2 C139.2 C140.2 C141.2 C142.2 C143.2 C144.2 C146.2 C147.2 C150.2 C152.2 C154.1 C156.1 C158.1 C160.1 C161.1 C162.1 C163.1 C164.2 C165.1 C166.1 DS6.2 DS7.2 DS9.2 J1.4 J1.8 J1.10 J1.12 J2.B5 J2.B7 J2.B9 J2.B11 J2.B17 J2.B19 J2.D6 J2.D8 J2.D10 J2.D16 J2.D18 J2.D20 J2.D22 J2.F1 J2.F3 J2.F5 J2.F7 J2.F9 J2.F11 J2.F13 J2.F15 J2.F17 J2.F19 J2.F21 J2.F23 J2.F25 J3.2 J3.3 JP3.1 JP3.10 JP4.2 JP4.10 JP5.2 JP5.10 Q1.3 R15.2 R17.1 R18.2 R19.2 R20.2 R21.2 R22.1 R23.1 R28.1 R39.2 R59.1 R60.1 R65.1 R67.1 R83.1 R84.1 S2.1 U1.A1 U1.A3 U1.A6 U1.A8 U1.A12 U1.A14 U1.A19 U1.A22 U1.A26 U1.AA4 U1.AA5 U1.AA8 U1.AA10 U1.AA11 U1.AA13 U1.AA14 U1.AA16 U1.AA17 U1.AA19 U1.AA22 U1.AB1 U1.AB2 U1.AB4 U1.AB6 U1.AB9 U1.AB18 U1.AB21 U1.AB26 U1.AC3 U1.AC5 U1.AC18 U1.AC22 U1.AC24 U1.AD2 U1.AD4 U1.AD18 U1.AE3 U1.AE8 U1.AE10 U1.AE12 U1.AE14 U1.AE19 U1.AE24 U1.AF1 U1.AF7 U1.AF9 U1.AF11 U1.AF13 U1.AF15 U1.AF19 U1.AF22 U1.AF26 U1.B3 U1.B6 U1.B7 U1.B13 U1.B19 U1.C2 U1.C4 U1.C13 U1.C18 U1.C23 U1.D1 U1.D2 U1.D5 U1.D13 U1.D18 U1.D22 U1.D24 U1.E3 U1.E6 U1.E9 U1.E16 U1.E18 U1.E21 U1.E23 U1.E26 U1.F5 U1.F8 U1.F10 U1.F11 U1.F13 U1.F14 U1.F16 U1.F17 U1.F19 U1.F22 U1.G9 U1.G12 U1.G15 U1.G18 U1.H1 U1.H6 U1.H21 U1.H26 U1.J5 U1.J7 U1.J20 U1.J22 U1.K6 U1.K21 U1.L1 U1.L6 U1.L21 U1.M7 U1.M13 U1.M15 U1.M20 U1.N5 U1.N6 U1.N12 U1.N14 U1.N21 U1.N25 U1.P2 U1.P6 U1.P13 U1.P15 U1.P21 U1.R7 U1.R12 U1.R14 U1.R20 U1.T1 U1.T5 U1.T6 U1.T21 U1.T26 U1.U6 U1.U21 U1.V5 U1.V7 U1.V20 U1.V22 U1.W1 U1.W6 U1.W21 U1.W26 U1.Y9 U1.Y12 U1.Y15 U1.Y18 U2.10 U2.30 U2.31 U2.40 U2.52 U2.69 U2.71 U2.80 U2.89 U2.91 U2.96 U2.102 U2.109 U2.111 U2.129 U2.142 U2.150 U2.151 U2.171 U2.190 U2.192 U2.199 U2.205 U2.210 U2.212 U2.221 U2.230 U2.232 U3.D4 U3.D5 U3.D6 U3.D7 U3.E4 U3.E5 U3.E6 U3.E7 U3.F4 U3.F5 U3.F6 U3.F7 U3.G4 U3.G5 U3.G6 U3.G7 U4.2 U5.4 U6.2 U7.27 U7.46 U7.47 U8.6 U8.12 U8.32 U8.38 U8.44 U8.46 U8.52 U8.58 U8.72 U8.78 U8.84 U8.86 U9.8 U9.17 U9.32 U9.41 U9.47 U9.48 U10.8 U10.17 U10.32 U10.41 U10.47 U10.48 U11.8 U11.17 U11.32 U11.41 U11.47 U11.48 U14.3 U15.1 U15.11 U15.12 U15.13 U16.2@5767,9727 U17.2@5029,9510 U18.2 U19.2 U19.3 U19.5 U19.18 U19.19 U19.35 U19.38 U19.44 U20.2 U21.2 U22.5 U23.2 | length 8598.5
  TopLayer w6: R59.1@7233.46,8660 v1(7288,8660)
  TopLayer w8: U2.190@4821.09,7619.78 4856,7654.7 4856,7689 v1(4916,7749) ; U2.171@4821.09,7994.22 4854.3,7961 4888,7961 v1(4944,7905) ; v1(5063,7304.92) U2.210@5099.48,7341.4 ; U2.151@5099.48,8272.6 5128.16,8243.92 v1(5156,8243.92) U2.150@5113.4,8286.52 ; U2.129@5405.7,8578.83 5440.54,8544 5462,8544 v1(5500.7,8505.3) ; v1(5664.46,8515.46) 5684,8535 5736.3,8535 U2.111@5766.22,8564.91 ; v1(5674.6,7140.7) U2.10@5766.22,7049.09 ; U2.30@6044.6,7327.48 v1(5986.08,7386) 6013.92,7386 U2.31@6058.52,7341.4 ; U2.91@6044.6,8286.52 6070.08,8312 6082,8312 6090,8304 v1(6107,8304) ; v1(6259.99,7724.54) U2.52@6350.83,7633.7 ; U2.69@6350.83,7980.3 v1(6388,8017.46)
  TopLayer w12: U2.192@4848.93,7591.94 4876.98,7620 4894,7620 v2(4959,7685) ; U2.199@4946.36,7494.51 4973.85,7522 4993,7522 v2(5056,7585) ; U2.205@5029.88,7410.99 5058.89,7440 5076,7440 v2(5138,7502) ; U2.212@5127.31,7313.56 5152.76,7339 5180,7339 5247,7406 v2(5247,7424.08) ; U2.221@5252.59,7188.28 5283.31,7219 5315,7219 v2(5360.7,7264.7) ; U2.230@5377.86,7063.01 5406.86,7092 5452,7092 v2(5484.54,7124.54) ; v2(5710,8430) 5768,8488 5768,8511.02 U2.109@5794.06,8537.07 ; v2(5818,8330) 5864,8376 5864,8412.15 U2.102@5891.49,8439.64 ; v2(5904,8248) 5951,8295 5951,8332.11 U2.96@5975.01,8356.12 ; v1(5940,8870) R17.1@5940,8926.54 ; v2(5988,8145) 6043,8200 6043,8229.24 U2.89@6072.44,8258.69 ; v2(6120.46,8035.46) 6167,8082 6167,8102.69 U2.80@6197.72,8133.41 ; v2(6259.46,7895.46) 6292,7928 6292,7977.14 U2.71@6322.99,8008.14 ; v1(6409,8360) C20.1@6546.54,8360 ; v2(6579,6909) U4.2@6579,6958 ; v2(6644,6911) U4.2@6644,6957 ; C26.1@6906.54,7980 6906.54,8042.54 v2(6936,8072) ; C19.1@8232.46,9093.46 8256.46,9093.46 v2(8271,9108)
  TopLayer w24: C139.2@4655,9621.12 v2(4655,9691) ; C127.1@4775,9579.46 v2(4775,9645) ; v2(4924,9246) C143.2@4999.88,9246 ; v2(4971,9366) C132.1@5041.54,9366 5032,9375.54 U17.2@5032,9507 ; C136.2@5398,9602.12 v2(5398,9661) ; C96.1@5518,9560.46 v2(5518,9620) ; v2(5696,9247) C137.2@5762.88,9247 ; v2(5727,9367) C125.1@5784.54,9367 5767,9384.54 5767,9497
  BottomLayer w6: v1(8633,8340) R83.1@8686.54,8340 ; R84.1@8686.54,8140 v1(8686.54,8180.46) ; U1.L1@8820,7386.3 8954.7,7386.3
  BottomLayer w8: C98.2@4904.54,7784.54 4916,7773.08 v1(4916,7749) ; C108.2@4920.7,7879.3 4944,7902.6 v1(4944,7905) ; v1(5156,8243.92) 5163.76,8236.16 C103.2@5163.76,8205.31 ; C99.2@5180.7,7480.7 v1(5206,7506) ; C97.2@5500.7,8459.3 v1(5500.7,8505.3) ; C105.2@5560.7,7120.7 v1(5584,7144) ; C119.2@5605.54,8515.46 v1(5664.46,8515.46) ; C104.2@5639.3,7140.7 v1(5674.6,7140.7) ; C115.2@5924.54,7364.54 5946,7386 v1(5986.08,7386) ; v1(6107,8304) 6152,8349 6152,8377.08 C114.2@6124.54,8404.54 ; C109.2@6215.46,7724.54 v1(6259.99,7724.54) ; v1(6251,7811) C110.2@6275.46,7835.46 ; U1.H1@8820,7504.41 v1(8850.41,7504.41)
  BottomLayer w12: C100.2@4944.54,7724.54 4959,7710.08 v2(4959,7685) ; C106.2@5044.54,7624.54 5056,7613.08 v2(5056,7585) ; C111.2@5124.54,7544.54 5138,7531.08 v2(5138,7502) ; C116.2@5224.54,7446.54 v2(5247,7424.08) ; v2(5360.7,7264.7) C123.2@5360.7,7320.7 ; v2(5484.54,7124.54) C120.2@5484.54,7184.54 ; C124.2@5659.3,8439.3 v2(5710,8430) ; C112.2@5759.3,8339.3 5768.6,8330 v2(5818,8330) ; C101.2@5859.3,8259.3 5870.6,8248 v2(5904,8248) ; C121.2@5948,8150.6 5953.6,8145 v2(5988,8145) ; C117.2@6055.46,8035.46 v2(6120.46,8035.46) ; C107.2@6195.46,7895.46 v2(6259.46,7895.46) ; C21.1@6580,7893.46 6616.54,7930 v1(6642,7930) 6643.18,7928.82 U8.58@6710,7928.82 ; C22.1@6600,7626.54 v1(6648.11,7674.65) ; v2(6614,7763) 6661.71,7810.71 U8.52@6710,7810.71 ; v1(6646,8310) 6658.52,8322.52 U8.78@6710,8322.52 ; U8.44@6710,7653.23 6669.53,7653.23 v1(6648.11,7674.65) ; U8.46@6710,7692.6 6666.06,7692.6 v1(6648.11,7674.65) ; U8.72@6710,8204.41 6793.41,8204.41 6820,8231 v1(6820,8253) ; U8.84@6710,8440.63 6660.37,8440.63 6649,8452 6649,8464 6665,8480 U8.86@6710,8480 v1(6710,8505) ; C24.1@7006.54,8580 6999,8572.46 v1(6999,8508) 7125.43,8381.58 U8.6@7180,8381.58 ; v1(7030,8290) 7056.53,8263.47 U8.12@7180,8263.47 ; v1(7253.46,8511.54) C23.1@7253.46,8580 ; v2(7557,9531) v2(7803,9531) ; v1(7792.84,7189.45) U1.T26@7835.75,7189.45 ; v1(7802.68,7622.52) U1.E26@7835.75,7622.52 ; v1(7808.58,7504.41) U1.H26@7835.75,7504.41 ; U1.W26@7835.75,7071.34 v1(7853.94,7053.15) ; C135.2@7845,9585 v2(7845,9641) ; v1(7857.28,7325.39) U1.N25@7875.12,7307.56 ; C135.2@7885,9587 v2(7885,9644) ; C95.1@7984,9540.46 v2(8030.46,9540.46) 8062.6,9572.6 Q1.3@8062.6,9590.79 ; v2(8127,8739) 8127,8760 8146.69,8779.68 U7.47@8195.28,8779.68 U7.46@8195.28,8799.37 ; v2(8145,8424) DS9.2@8216.6,8424 ; U7.27@8195.28,9173.39 8255.61,9173.39 8271,9158 v2(8271,9108) ; U15.1@8780,9439 8833.46,9385.54 R67.1@8833.46,9359 ; v2(9240,9413) C146.2@9240,9463.88 ; R65.1@9253.46,9039 v2(9307,9039) ; C64.1@9253.46,9339 9253.46,9287.54 v2(9256,9285) C54.1@9256,9237 ; v2(9370,9282) C134.2@9370,9340 ; v2(9442,9277) C134.2@9442,9345
  other v2: 8813.99,9405.01 7226,9430 7388,9431 8888,9514 8930,9514 8887,9579 8929,9580 7222,9618 7389,9618 8886,9651 8931,9651 5767,9727 5032,9737
GP02: R86.1 U1.C6 | length 502
  TopLayer w6: v1(8643,7721.11) 8643,7823 v1(8670,7850)
  BottomLayer w6: R86.1@8580,8146.54 8670,8056.54 v1(8670,7850) ; U1.C6@8623.15,7701.26 v1(8643,7721.11)
GP04: U1.F4 U2.104 | length 4036.5
  TopLayer w6: U2.104@5863.65,8467.48 5943.18,8547 8117,8547 8137,8527 v1(8176,8527) ; v1(8721.74,7603) 8741.74,7623 8811,7623 8820,7632 8820,7720 v1(8891,7791)
  BottomLayer w6: v1(8176,8527) 8715,8527 8901,8341 8901,7921 ; U1.F4@8701.89,7583.15 v1(8721.74,7603)
  BottomLayer w8: v1(8891,7791) 8891,7911 8901,7921
GP05: U1.F3 U2.107 | length 4206.9
  TopLayer w6: U2.107@5821.89,8509.23 5908.66,8596 8189,8596 v1(8204,8581)
  BottomLayer w6: v1(8204,8581) 8723,8581 8949,8355 8949,7671 8842,7564 8760.41,7564 U1.F3@8741.26,7583.15
GP06: U1.F2 U2.106 | length 4087.1
  TopLayer w6: U2.106@5835.81,8495.32 5921.5,8581 8159,8581 v1(8177,8563)
  BottomLayer w6: v1(8177,8563) 8721,8563 8932,8352 8932,7685 8850,7603 8800.48,7603 U1.F2@8780.63,7583.15
GP07: U1.E1 U2.105 | length 3971.2
  TopLayer w6: U2.105@5849.73,8481.4 5932.34,8564 8135,8564 8154,8545 v1(8210,8545)
  BottomLayer w6: v1(8210,8545) 8719,8545 8918,8346 8918,7696 8844.52,7622.52 U1.E1@8820,7622.52
IN1+: C2.1 R11.1 U3.A7 | length 1215.2
  TopLayer w8: C2.1@4553.46,6540 4595,6498.46 4595,6323 4735,6183 5391,6183 5453.78,6245.78 U3.A7@5453.78,6284
IN1-: C1.1 R11.2 U3.B7 | length 1314
  TopLayer w8: C1.1@4553.46,6640 4609,6584.46 4609,6333 4744,6198 5382,6198 5434,6250 5434,6303.59 U3.B7@5453.78,6323.37
IN2+: C30.1 R53.1 U3.A2 | length 628.7
  TopLayer w6: v1(5650.63,6259.37) U3.A2@5650.63,6284
  BottomLayer w6: v1(5650.63,6259.37) 5671,6239 5771,6239 5948,6416 6031.54,6416 R53.1@6058,6389.54 C30.1@6145,6389.54 ; C30.1@6150.46,6395 C30.1@6145,6389.54 ; C30.1@6151.54,6383 C30.1@6145,6389.54
IN2-: C29.1 R8.1 R53.2 U3.B2 | length 641.4
  TopLayer w6: U3.B2@5650.63,6323.37 v1(5670,6304)
  BottomLayer w6: v1(5670,6304) 5670,6275 5690,6255 5758,6255 5935.46,6432.46 6034,6432.46 R53.2@6058,6456.46 6130,6456.46 C29.1@6153.54,6480
JTAG_TCK: JP4.1 R17.2 U2.147 | length 1240.1
  TopLayer w6: v1(5124,8385) 5124,8359.44 U2.147@5155.15,8328.28
  TopLayer w12: JP4.1@5740,9020 5760,9040 5893.46,9040 R17.2@5940,8993.46
  BottomLayer w6: v1(5124,8385) 5124,8398 5573,8847 5663,8847 5687,8871 5687,8967 JP4.1@5740,9020
JTAG_TDI: JP4.9 R14.1 U2.155 | length 1158.2
  TopLayer w6: v1(5005,8255.73) U2.155@5043.8,8216.93
  TopLayer w12: R14.1@5286.54,9160 5286.54,9073.46 JP4.9@5340,9020
  BottomLayer w6: v1(5005,8255.73) 5005,8368 5386,8749 5386,8974 JP4.9@5340,9020
JTAG_TDO: JP4.3 U2.149 | length 1138.2
  TopLayer w6: v1(5063,8364.76) U2.149@5127.31,8300.44
  BottomLayer w6: v1(5063,8364.76) 5063,8396 5488,8821 5488,9050 5514,9076 5584,9076 JP4.3@5640,9020
JTAG_TMS: JP4.5 R16.1 U2.148 | length 1106.9
  TopLayer w6: v1(5103,8352.6) U2.148@5141.23,8314.36 ; JP4.5@5547,9027 JP4.5@5553.46,9033.46
  TopLayer w12: JP4.5@5540,9020 5553.46,9033.46 R16.1@5553.46,9160
  BottomLayer w6: v1(5103,8352.6) 5090,8365.6 5090,8394 5587,8891 5587,8973 JP4.5@5540,9020
LVDS1_INN: JP1.1 R43.1 U2.179 | length 663.1
  TopLayer w8: JP1.1@4240,7600 4453.46,7600 R43.1@4480,7626.54 4509.54,7626.54 4557,7674 4591,7674 4738,7821 4738,7854.59 U2.179@4709.73,7882.86
LVDS1_INP: JP1.2 R43.2 U2.180 | length 1081.9
  TopLayer w8: JP1.2@4338.43,7501.57 JP1.2@4141.57,7501.57 JP1.2@4141.57,7698.43 JP1.2@4338.43,7698.43 4343.39,7693.46 4584.46,7693.46 4722,7831 4722,7842.75 U2.180@4695.81,7868.94
LVDS1_OUTN: JP10.3 R7.1 R10.1 | length 267.4
  TopLayer w8: JP10.3@4869.29,8550.71 4923.38,8550.71 R7.1@4976.34,8603.66 4983.66,8603.66 R10.1@5076.34,8696.34
LVDS1_OUTP: JP10.1 R7.2 R9.1 | length 261.1
  TopLayer w8: JP10.1@4940,8480 4947.33,8480 R7.2@5023.66,8556.34 5056.34,8556.34 R9.1@5136.34,8636.34
LVDS2_INN: JP2.1 R42.1 U2.177 | length 542.8
  TopLayer w8: JP2.1@4240,8020 4453.46,8020 4531.46,7942 4706.27,7942 U2.177@4737.57,7910.7
LVDS2_INP: JP2.2 R42.2 U2.178 | length 990.2
  TopLayer w8: JP2.2@4338.43,8118.43 JP2.2@4141.57,8118.43 JP2.2@4141.57,7921.57 JP2.2@4338.43,7921.57 4343.39,7926.54 4693.9,7926.54 U2.178@4723.65,7896.78
LVDS2_OUTN: JP10.7 R4.1 R6.1 | length 248.2
  TopLayer w8: JP10.7@4727.87,8692.13 4764.81,8692.13 R4.1@4836.34,8763.66 4843.66,8763.66 R6.1@4916.34,8836.34
LVDS2_OUTP: JP10.5 R4.2 R5.1 | length 247.7
  TopLayer w8: JP10.5@4798.58,8621.42 4798.58,8631.25 R4.2@4883.66,8716.34 4916.34,8716.34 R5.1@4976.34,8776.34
LVDS3_INN: JP7.1 R77.1 U2.173 | length 818.2
  TopLayer w8: JP7.1@4240,8440 4433.47,8440 R77.1@4480,8393.46 4560,8313.46 4560,8196 4789.62,7966.38 U2.173@4793.25,7966.38
LVDS3_INP: JP7.2 R77.2 U2.174 | length 1236.4
  TopLayer w8: JP7.2@4338.43,8341.58 JP7.2@4141.57,8341.58 JP7.2@4141.57,8538.42 JP7.2@4338.43,8538.42 ; JP7.2@4353.47,8326.53 R77.2@4480,8326.54 4542,8264.54 4542,8189.79 U2.174@4779.33,7952.46
  TopLayer w20: JP7.2@4338.43,8341.58 JP7.2@4353.46,8326.54
LVDS3_OUTN: JP10.11 R1.1 R3.1 | length 249
  TopLayer w8: JP10.11@4586.45,8833.55 4626.23,8833.55 R1.1@4696.34,8903.66 4703.66,8903.66 R3.1@4776.34,8976.34
LVDS3_OUTP: JP10.9 R1.2 R2.1 | length 246.9
  TopLayer w8: JP10.9@4657.16,8762.84 4743.66,8849.35 R1.2@4743.66,8856.34 4776.34,8856.34 R2.1@4836.34,8916.34
LVDS4_INN: JP10.12 R44.1 U2.168 | length 959.7
  TopLayer w8: JP10.12@4515.74,8762.84 4588.16,8762.84 4640,8711 4640,8670 4583.66,8613.66 R44.1@4583.66,8543.66 4617,8510.33 4617,8281.82 U2.168@4862.85,8035.97
LVDS4_INP: JP10.10 R44.2 U2.169 | length 776
  TopLayer w8: R44.2@4536.34,8496.34 4536.34,8642.02 JP10.10@4586.45,8692.13 ; 4599,8478 4599,8271.98 U2.169@4848.93,8022.06
LVDS5_INN: JP10.8 R45.1 U2.166 | length 729.3
  TopLayer w8: JP10.8@4657.16,8621.42 4728.58,8621.42 4779,8571 4779,8528 4739,8488 4739,8368.33 R45.1@4763.66,8343.66 4763.66,8190.83 U2.166@4890.68,8063.81
LVDS5_INP: JP10.6 R45.2 U2.167 | length 572
  TopLayer w8: JP10.6@4727.87,8550.71 4721,8543.84 4721,8301 R45.2@4716.34,8296.34 4744,8268.67 4744,8182.66 U2.167@4876.77,8049.89
LVDS6_INN: JP10.4 R46.1 U2.164 | length 509.3
  TopLayer w8: JP10.4@4798.58,8480 4867,8480 4923.66,8423.34 4923.66,8204.66 4886,8167 4886,8124.18 U2.164@4918.52,8091.65
LVDS6_INP: JP10.2 R46.2 U2.165 | length 346.2
  TopLayer w8: JP10.2@4869.29,8409.29 4869.29,8113.05 U2.165@4904.6,8077.73
NCE: JP5.6 R28.2 U2.33 | length 1768.7
  TopLayer w6: U2.33@6086.36,7369.23 v1(6332,7123.6)
  BottomLayer w6: v1(6332,7123.6) 6362,7093.6 6362,6589 6641,6310 7050,6310 JP5.6@7100,6260
NCEO: U2.32
NetC27_1: C27.1 JP11.1 | length 359.7
  BottomLayer w6: C27.1@6093.46,6260 6122.46,6231 6369,6231 JP11.1@6420,6180
NetC28_1: C28.1 JP11.2 | length 234.8
  BottomLayer w6: C28.1@6093.46,6160 6300,6160 JP11.2@6320,6180
NetC29_2: C29.2 JP11.3 | length 282.7
  BottomLayer w6: C29.2@6220.46,6480 6420,6280.46 JP11.3@6420,6280
NetC30_2: C30.2 JP11.4 | length 145.1
  BottomLayer w6: C30.2@6218.46,6383 6218.46,6381.54 JP11.4@6320,6280
NetC42_2: C42.2 C43.2 C44.2 C50.2 C51.2 C52.2 C53.2 C60.2 C61.2 C62.2 C63.1 C70.2 C71.2 C72.2 C78.1 C79.2 C80.2 C81.2 C87.2 C88.2 C89.2 C90.1 C91.1 C92.1 C93.1 C94.1 C145.2 C148.2 C149.2 C151.2
NetC54_2: C54.2 U15.18 | length 361.7
  BottomLayer w12: U15.18@9039.84,9490.18 9124.82,9490.18 9145,9470 9145,9280.54 C54.2@9186.54,9239
NetC64_2: C64.2 U15.17 | length 298
  BottomLayer w12: U15.17@9039.84,9515.77 9143.08,9515.77 9172.85,9486 9172.85,9352.69 C64.2@9186.54,9339
NetC102_1: C102.1 U15.5 | length 101.7
  TopLayer w12: C102.1@8680,9545.54 8684.17,9541.36 v2(8715.36,9541.36)
  BottomLayer w12: v2(8715.36,9541.36) U15.5@8780,9541.36
NetC102_2: C102.2 L1.1 U15.6 U15.7 U15.8 U15.9 U15.10 | length 54.3
  TopLayer w12: v2(8628,9618) 8633.54,9612.46 C102.2@8680,9612.46
NetC113_1: C113.1 C118.1 C122.1 R67.2 R70.1 U15.2 | length 844.8
  BottomLayer w12: U15.2@8780,9464.59 8715.59,9464.59 8703,9452 8703,9422.54 8833.46,9292.07 8833.46,9179 C122.1@8753.46,9099 8853.46,9099 C118.1@8940,9185.54 C113.1@9040,9185.54
NetC113_2: C113.2 R68.1 | length 117.5
  BottomLayer w12: R68.1@9013.46,9359 9040,9332.46 C113.2@9040,9252.46
NetC118_2: C118.2 R68.2 U15.3 | length 350
  BottomLayer w12: U15.3@8780,9490.18 8834.82,9490.18 8843,9482 8843,9448 8932,9359 R68.2@8946.54,9359 8946.54,9259 C118.2@8940,9252.46
NetC122_2: C122.2 R69.1 | length 113.1
  BottomLayer w12: R69.1@8573.46,9099 C122.2@8686.54,9099
NetC160_2: C160.2 C161.2 FB3.2 U21.4 | length 324.9
  BottomLayer w12: U21.4@8762,6181 8763,6180 C160.2@8886.54,6180 C161.2@8886.54,6280 FB3.2@8886.54,6380
NetC163_2: C163.2 C164.1 U1.V6 U20.3 | length 873.6
  BottomLayer w6: C163.2@8393.46,6620 8465,6620 8603,6758 8603,7090.56 U1.V6@8623.15,7110.71
  BottomLayer w12: C163.2@8393.46,6620 8393.46,6501.65 8400,6495.12 U20.3@8400,6376.85
NetDS1_2: DS1.2 R15.1
NetDS2_2: DS2.2 R18.1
